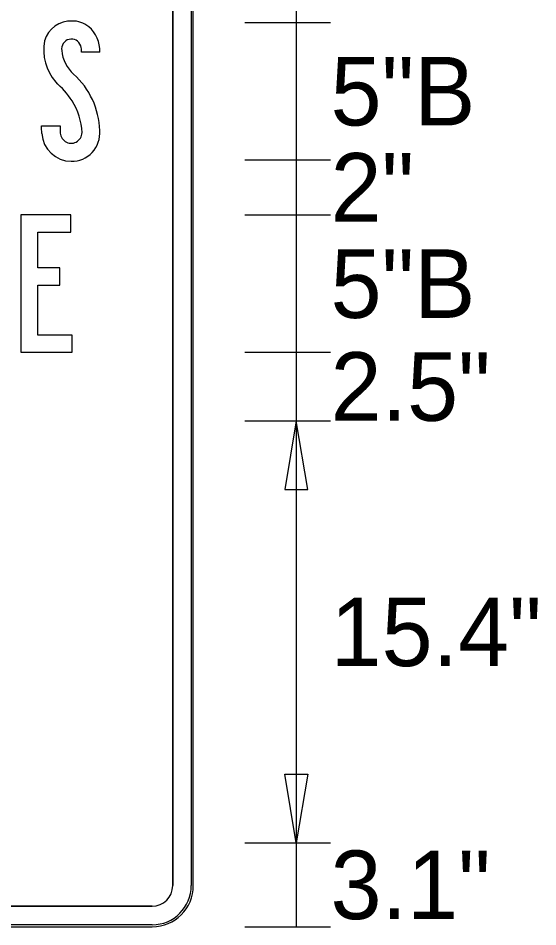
# Model space of a CAD drawing. Extents: x 17890628 to 17890844, y 17897693 to 17898031.
# Drawn here: x 17890752.65 to 17890757.7, y 17897982.65 to 17897991.48 of the extents above; entities that cross this region are included whole.
import ezdxf

# ---------------------------------------------------------------- set-up
doc = ezdxf.new("R2010")
doc.units = 0
for name, color, linetype in [('GSColorFill', 7, 'Continuous'), ('GSDims', 7, 'Continuous'), ('GSOutline', 7, 'Continuous')]:
    doc.layers.add(name, color=color, linetype=linetype)

msp = doc.modelspace()

# ---------------------------------------------------------------- linework, layer by layer
at = {"layer": 'GSColorFill'}
for p, q in [((17890754.1502, 17897991.8468), (17890754.1502, 17897983.0468)), ((17890754.3302, 17897991.8468), (17890754.3302, 17897983.0468)), ((17890754.3502, 17897983.0468), (17890754.3502, 17897991.8468)), ((17890754.3502, 17897983.0468), (17890754.3502, 17897991.8468)), ((17890754.3502, 17897983.0468), (17890754.3502, 17897991.8468)), ((17890753.4406, 17897991.1466), (17890753.2635, 17897991.1466)), ((17890753.4406, 17897991.1466), (17890753.2635, 17897991.1466)), ((17890753.4406, 17897991.1466), (17890753.2635, 17897991.1466)), ((17890752.8759, 17897990.431), (17890753.0572, 17897990.431)), ((17890752.8759, 17897990.431), (17890753.0572, 17897990.431)), ((17890752.8759, 17897990.431), (17890753.0572, 17897990.431)), ((17890753.9502, 17897982.8468), (17890746.7522, 17897982.8468)), ((17890753.9502, 17897982.6668), (17890746.7504, 17897982.6668)), ((17890746.7502, 17897982.6468), (17890753.9502, 17897982.6468)), ((17890746.7504, 17897982.6468), (17890753.9502, 17897982.6468)), ((17890746.7522, 17897982.6468), (17890753.9502, 17897982.6468))]:
    msp.add_line(p, q, dxfattribs=at)
msp.add_lwpolyline([(17890752.8389, 17897988.3972), (17890752.8389, 17897988.8832), (17890753.0535, 17897988.8832), (17890753.0535, 17897989.0499), (17890752.8389, 17897989.0499), (17890752.8389, 17897989.3972), (17890753.1592, 17897989.3972), (17890753.1592, 17897989.5639), (17890752.6748, 17897989.5639), (17890752.6748, 17897988.2306), (17890753.1738, 17897988.2306), (17890753.1738, 17897988.3972)], close=True, dxfattribs=at)
msp.add_lwpolyline([(17890752.8389, 17897988.3972), (17890752.8389, 17897988.8832), (17890753.0535, 17897988.8832), (17890753.0535, 17897989.0499), (17890752.8389, 17897989.0499), (17890752.8389, 17897989.3972), (17890753.1592, 17897989.3972), (17890753.1592, 17897989.5639), (17890752.6748, 17897989.5639), (17890752.6748, 17897988.2306), (17890753.1738, 17897988.2306), (17890753.1738, 17897988.3972)], close=True, dxfattribs=at)
msp.add_lwpolyline([(17890752.8389, 17897988.3972), (17890752.8389, 17897988.8832), (17890753.0535, 17897988.8832), (17890753.0535, 17897989.0499), (17890752.8389, 17897989.0499), (17890752.8389, 17897989.3972), (17890753.1592, 17897989.3972), (17890753.1592, 17897989.5639), (17890752.6748, 17897989.5639), (17890752.6748, 17897988.2306), (17890753.1738, 17897988.2306), (17890753.1738, 17897988.3972)], close=True, dxfattribs=at)
for radius, end in [(0.4, 0), (0.4, 0), (0.2, 360), (0.4, 0), (0.38, 0)]:
    msp.add_arc((17890753.9502, 17897983.0468), radius, 270, end, dxfattribs=at)
for centre, major_axis, start_param, end_param in [((17890753.1607, 17897991.1788), (0, 0.2705), 6.238773, 7.56343), ((17890753.1607, 17897991.1788), (0, 0.2705), 6.238773, 7.56343), ((17890753.1607, 17897991.1788), (0, 0.2705), 6.238773, 7.56343), ((17890753.1782, 17897991.1961), (0, 0.253), 5.608184, 6.306169), ((17890753.1782, 17897991.1961), (0, 0.253), 5.608184, 6.306169), ((17890753.1782, 17897991.1961), (0, 0.253), 5.608184, 6.306169), ((17890753.1462, 17897991.1628), (0, 0.2993), 4.658508, 5.592972), ((17890753.1462, 17897991.1628), (0, 0.2993), 4.658508, 5.592972), ((17890753.1462, 17897991.1628), (0, 0.2993), 4.658508, 5.592972), ((17890753.3518, 17897991.1655), (0, 0.4622), 1.37325, 2.303641), ((17890753.3518, 17897991.1655), (0, 0.4622), 1.37325, 2.303641), ((17890753.3518, 17897991.1655), (0, 0.4622), 1.37325, 2.303641), ((17890753.1662, 17897991.1763), (0, 0.0973), 5.044718, 8.004311), ((17890753.1662, 17897991.1763), (0, 0.0973), 5.044718, 8.004311), ((17890753.1662, 17897991.1763), (0, 0.0973), 5.044718, 8.004311), ((17890753.4154, 17897991.1963), (0, 0.3509), 1.669462, 2.420236), ((17890753.4154, 17897991.1963), (0, 0.3509), 1.669462, 2.420236), ((17890753.4154, 17897991.1963), (0, 0.3509), 1.669462, 2.420236), ((17890753.11, 17897991.1603), (0, 0.1565), 4.624973, 5.022668), ((17890753.11, 17897991.1603), (0, 0.1565), 4.624973, 5.022668), ((17890753.11, 17897991.1603), (0, 0.1565), 4.624973, 5.022668), ((17890752.6852, 17897990.3578), (0, 0.7684), 4.746366, 5.558127), ((17890752.6852, 17897990.3578), (0, 0.7684), 4.746366, 5.558127), ((17890752.6852, 17897990.3578), (0, 0.7684), 4.746366, 5.558127), ((17890752.2664, 17897990.0195), (0, 1.1294), 5.330576, 5.546891), ((17890752.2664, 17897990.0195), (0, 1.1294), 5.330576, 5.546891), ((17890752.2664, 17897990.0195), (0, 1.1294), 5.330576, 5.546891), ((17890752.6473, 17897990.3338), (0, 0.6329), 4.761194, 5.279997), ((17890752.6473, 17897990.3338), (0, 0.6329), 4.761194, 5.279997), ((17890752.6473, 17897990.3338), (0, 0.6329), 4.761194, 5.279997), ((17890740.3714, 17897990.1593), (0, 12.6979), 4.727928, 4.733783), ((17890740.3714, 17897990.1593), (0, 12.6979), 4.727928, 4.733783), ((17890740.3714, 17897990.1593), (0, 12.6979), 4.727928, 4.733783), ((17890753.8141, 17897990.4119), (0, 0.7687), 1.545917, 1.619781), ((17890753.8141, 17897990.4119), (0, 0.7687), 1.545917, 1.619781), ((17890753.8141, 17897990.4119), (0, 0.7687), 1.545917, 1.619781), ((17890753.1642, 17897990.3776), (0, 0.292), 1.642579, 3.144332), ((17890753.1642, 17897990.3776), (0, 0.292), 1.642579, 3.144332), ((17890753.1642, 17897990.3776), (0, 0.292), 1.642579, 3.144332), ((17890753.1638, 17897990.3686), (0, 0.1078), 1.518722, 4.675676), ((17890753.1638, 17897990.3686), (0, 0.1078), 1.518722, 4.675676), ((17890753.1638, 17897990.3686), (0, 0.1078), 1.518722, 4.675676), ((17890753.1689, 17897990.3632), (0, 0.2777), 3.127116, 4.786666), ((17890753.1689, 17897990.3632), (0, 0.2777), 3.127116, 4.786666), ((17890753.1689, 17897990.3632), (0, 0.2777), 3.127116, 4.786666)]:
    msp.add_ellipse(centre, major_axis=major_axis, ratio=0.985, start_param=start_param, end_param=end_param, dxfattribs=at)
at = {"layer": 'GSDims'}
for p, q in [((17890755.3502, 17897992.2472), (17890755.3502, 17897991.4339)), ((17890754.8502, 17897991.4339), (17890755.6835, 17897991.4339)), ((17890754.8502, 17897991.4339), (17890755.6835, 17897991.4339)), ((17890755.3502, 17897991.4339), (17890755.3502, 17897990.1006)), ((17890754.8502, 17897990.1006), (17890755.6835, 17897990.1006)), ((17890754.8502, 17897990.1006), (17890755.6835, 17897990.1006)), ((17890755.3502, 17897990.1006), (17890755.3502, 17897989.5639)), ((17890754.8502, 17897989.5639), (17890755.6835, 17897989.5639)), ((17890754.8502, 17897989.5639), (17890755.6835, 17897989.5639)), ((17890755.3502, 17897989.5639), (17890755.3502, 17897988.2306)), ((17890754.8502, 17897988.2306), (17890755.6835, 17897988.2306)), ((17890754.8502, 17897988.2306), (17890755.6835, 17897988.2306)), ((17890755.3502, 17897988.2306), (17890755.3502, 17897987.5639)), ((17890754.8502, 17897987.5639), (17890755.6835, 17897987.5639)), ((17890754.8502, 17897987.5639), (17890755.6835, 17897987.5639)), ((17890755.3502, 17897987.5639), (17890755.3502, 17897983.4631)), ((17890754.8502, 17897983.4631), (17890755.6835, 17897983.4631)), ((17890754.8502, 17897983.4631), (17890755.6835, 17897983.4631)), ((17890755.3502, 17897983.4631), (17890755.3502, 17897982.6468)), ((17890754.8502, 17897982.6468), (17890755.6835, 17897982.6468))]:
    msp.add_line(p, q, dxfattribs=at)
for points in [[(17890755.3502, 17897987.5639), (17890755.2391, 17897986.8972), (17890755.4613, 17897986.8972)], [(17890755.3502, 17897983.4631), (17890755.2391, 17897984.1298), (17890755.4613, 17897984.1298)]]:
    msp.add_lwpolyline(points, close=True, dxfattribs=at)
at = {"layer": 'GSOutline'}
for p, q in [((17890754.1502, 17897983.0468), (17890754.1502, 17897991.8468)), ((17890754.3502, 17897983.0468), (17890754.3502, 17897991.8468)), ((17890753.4406, 17897991.1466), (17890753.2635, 17897991.1466)), ((17890753.4406, 17897991.1466), (17890753.2635, 17897991.1466)), ((17890753.4406, 17897991.1466), (17890753.2635, 17897991.1466)), ((17890752.8759, 17897990.431), (17890753.0572, 17897990.431)), ((17890752.8759, 17897990.431), (17890753.0572, 17897990.431)), ((17890752.8759, 17897990.431), (17890753.0572, 17897990.431)), ((17890746.7502, 17897982.8468), (17890753.9502, 17897982.8468)), ((17890746.7502, 17897982.6468), (17890753.9502, 17897982.6468))]:
    msp.add_line(p, q, dxfattribs=at)
msp.add_lwpolyline([(17890752.8389, 17897988.3972), (17890752.8389, 17897988.8832), (17890753.0535, 17897988.8832), (17890753.0535, 17897989.0499), (17890752.8389, 17897989.0499), (17890752.8389, 17897989.3972), (17890753.1592, 17897989.3972), (17890753.1592, 17897989.5639), (17890752.6748, 17897989.5639), (17890752.6748, 17897988.2306), (17890753.1738, 17897988.2306), (17890753.1738, 17897988.3972)], close=True, dxfattribs=at)
for radius in [0.4, 0.2]:
    msp.add_arc((17890753.9502, 17897983.0468), radius, 270, 0, dxfattribs=at)
for centre, major_axis, start_param, end_param in [((17890753.1607, 17897991.1788), (0, 0.2705), 6.238773, 7.56343), ((17890753.1607, 17897991.1788), (0, 0.2705), 6.238773, 7.56343), ((17890753.1607, 17897991.1788), (0, 0.2705), 6.238773, 7.56343), ((17890753.1782, 17897991.1961), (0, 0.253), 5.608184, 6.306169), ((17890753.1782, 17897991.1961), (0, 0.253), 5.608184, 6.306169), ((17890753.1782, 17897991.1961), (0, 0.253), 5.608184, 6.306169), ((17890753.1462, 17897991.1628), (0, 0.2993), 4.658508, 5.592972), ((17890753.1462, 17897991.1628), (0, 0.2993), 4.658508, 5.592972), ((17890753.1462, 17897991.1628), (0, 0.2993), 4.658508, 5.592972), ((17890753.3518, 17897991.1655), (0, 0.4622), 1.37325, 2.303641), ((17890753.3518, 17897991.1655), (0, 0.4622), 1.37325, 2.303641), ((17890753.3518, 17897991.1655), (0, 0.4622), 1.37325, 2.303641), ((17890753.1662, 17897991.1763), (0, 0.0973), 5.044718, 8.004311), ((17890753.1662, 17897991.1763), (0, 0.0973), 5.044718, 8.004311), ((17890753.1662, 17897991.1763), (0, 0.0973), 5.044718, 8.004311), ((17890753.4154, 17897991.1963), (0, 0.3509), 1.669462, 2.420236), ((17890753.4154, 17897991.1963), (0, 0.3509), 1.669462, 2.420236), ((17890753.4154, 17897991.1963), (0, 0.3509), 1.669462, 2.420236), ((17890753.11, 17897991.1603), (0, 0.1565), 4.624973, 5.022668), ((17890753.11, 17897991.1603), (0, 0.1565), 4.624973, 5.022668), ((17890753.11, 17897991.1603), (0, 0.1565), 4.624973, 5.022668), ((17890752.6852, 17897990.3578), (0, 0.7684), 4.746366, 5.558127), ((17890752.6852, 17897990.3578), (0, 0.7684), 4.746366, 5.558127), ((17890752.6852, 17897990.3578), (0, 0.7684), 4.746366, 5.558127), ((17890752.2664, 17897990.0195), (0, 1.1294), 5.330576, 5.546891), ((17890752.2664, 17897990.0195), (0, 1.1294), 5.330576, 5.546891), ((17890752.2664, 17897990.0195), (0, 1.1294), 5.330576, 5.546891), ((17890752.6473, 17897990.3338), (0, 0.6329), 4.761194, 5.279997), ((17890752.6473, 17897990.3338), (0, 0.6329), 4.761194, 5.279997), ((17890752.6473, 17897990.3338), (0, 0.6329), 4.761194, 5.279997), ((17890740.3714, 17897990.1593), (0, 12.6979), 4.727928, 4.733783), ((17890740.3714, 17897990.1593), (0, 12.6979), 4.727928, 4.733783), ((17890740.3714, 17897990.1593), (0, 12.6979), 4.727928, 4.733783), ((17890753.8141, 17897990.4119), (0, 0.7687), 1.545917, 1.619781), ((17890753.8141, 17897990.4119), (0, 0.7687), 1.545917, 1.619781), ((17890753.8141, 17897990.4119), (0, 0.7687), 1.545917, 1.619781), ((17890753.1642, 17897990.3776), (0, 0.292), 1.642579, 3.144332), ((17890753.1642, 17897990.3776), (0, 0.292), 1.642579, 3.144332), ((17890753.1642, 17897990.3776), (0, 0.292), 1.642579, 3.144332), ((17890753.1638, 17897990.3686), (0, 0.1078), 1.518722, 4.675676), ((17890753.1638, 17897990.3686), (0, 0.1078), 1.518722, 4.675676), ((17890753.1638, 17897990.3686), (0, 0.1078), 1.518722, 4.675676), ((17890753.1689, 17897990.3632), (0, 0.2777), 3.127116, 4.786666), ((17890753.1689, 17897990.3632), (0, 0.2777), 3.127116, 4.786666), ((17890753.1689, 17897990.3632), (0, 0.2777), 3.127116, 4.786666)]:
    msp.add_ellipse(centre, major_axis=major_axis, ratio=0.985, start_param=start_param, end_param=end_param, dxfattribs=at)

# ---------------------------------------------------------------- texts
at = {"layer": 'GSDims'}
for s, p in [('5"B', (17890755.6835, 17897990.4339)), ('2"', (17890755.6835, 17897989.4989)), ('5"B', (17890755.6835, 17897988.5639)), ('2.5"', (17890755.6835, 17897987.5639)), ('15.4"', (17890755.6835, 17897985.1802)), ('3.1"', (17890755.6835, 17897982.7216))]:
    msp.add_text(s, height=0.66667, dxfattribs=at).set_placement(p)

doc.saveas('drawing.dxf')
